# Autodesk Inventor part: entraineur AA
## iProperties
Created: 2011-09
Part Number: entraineur AA
Document SubType Name: Modeling
Designer: A
Manufacturer: Standard
Standards Organization: Custom
Author: A
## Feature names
1. Extrusion1
2. Extrusion2
3. Perçage1 [Hole]
4. Perçage2 [Hole]
5. Perçage3 [Hole]
6. Extrusion3
